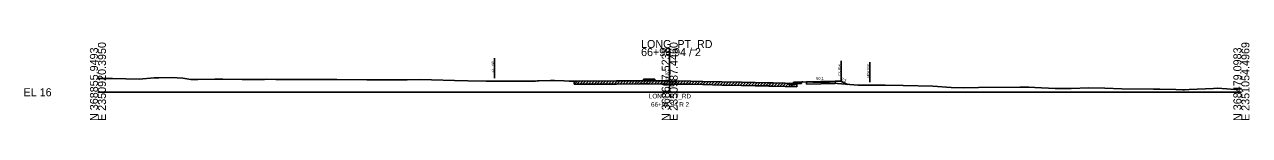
# Model space of a CAD drawing. Extents: x 974 to 2350744, y -10 to 368509.
# Drawn here: x 1974.3 to 2402.8, y 8990.3 to 9018.2 of the extents above; entities that cross this region are included whole.
import ezdxf

# ---------------------------------------------------------------- set-up
doc = ezdxf.new("R2010")
doc.units = 0
for name, color, linetype in [('RD_GPK_XS_Cell', 7, 'Continuous'), ('RD_PD_ConcMed', 7, 'Continuous'), ('RD_XS_CurbBase', 7, 'Continuous'), ('RD_XS_CurbFront', 7, 'Continuous'), ('RD_XS_CurbTop', 7, 'Continuous'), ('RD_XS_EarthShd', 7, 'Continuous'), ('RD_XS_ExGround', 7, 'Continuous'), ('RD_XS_ExPaveRet', 7, 'Continuous'), ('RD_XS_ExRW', 7, 'Continuous'), ('RD_XS_NewRW', 7, 'Continuous'), ('RD_XS_SW', 7, 'Continuous'), ('RD_XS_SWbase', 7, 'Continuous'), ('RD_XS_TieSlope', 7, 'Continuous'), ('RD_XS_TX_Elev_EX', 7, 'Continuous'), ('RD_XS_TX_Slope', 7, 'Continuous'), ('RD_XS_TX_Station', 7, 'Continuous'), ('RD_XS_TX_TOC', 7, 'Continuous')]:
    doc.layers.add(name, color=color, linetype=linetype)

msp = doc.modelspace()

# ---------------------------------------------------------------- linework, layer by layer
at = {"layer": 'RD_GPK_XS_Cell'}
for p, q in [((2200, 9000), (2200, 9015.4)), ((2000, 9000), (2200, 9000)), ((2200, 9000), (2400, 9000))]:
    msp.add_line(p, q, dxfattribs=at)
at = {"layer": 'RD_PD_ConcMed'}
for p, q in [((2190.85, 9004.54), (2194.85, 9004.53)), ((2190.85, 9004.04), (2190.85, 9004.54)), ((2194.85, 9004.03), (2194.85, 9004.53))]:
    msp.add_line(p, q, dxfattribs=at)
at = {"layer": 'RD_XS_CurbBase'}
for p, q in [((2243.86, 9003.55), (2243.86, 9002.55)), ((2243.28, 9002.55), (2241.86, 9002.63)), ((2243.86, 9002.55), (2243.28, 9002.55))]:
    msp.add_line(p, q, dxfattribs=at)
at = {"layer": 'RD_XS_CurbFront'}
msp.add_line((2241.86, 9002.63), (2241.86, 9003.13), dxfattribs=at)
at = {"layer": 'RD_XS_CurbTop'}
for p, q in [((2243.28, 9003.05), (2243.36, 9003.55)), ((2243.36, 9003.55), (2243.86, 9003.55)), ((2241.86, 9003.15), (2241.86, 9003.13)), ((2241.86, 9003.13), (2243.28, 9003.05))]:
    msp.add_line(p, q, dxfattribs=at)
at = {"layer": 'RD_XS_EarthShd'}
for p, q in [((2243.86, 9003.55), (2247.86, 9003.68)), ((2257.86, 9003.88), (2259.86, 9003.92))]:
    msp.add_line(p, q, dxfattribs=at)
at = {"layer": 'RD_XS_ExGround'}
msp.add_lwpolyline([(2000, 9004.77), (2001.58, 9004.78), (2002.13, 9004.82), (2005.1, 9004.74), (2014.42, 9004.54), (2019.72, 9005.02), (2021.34, 9005.07), (2025.69, 9005.13), (2029.73, 9004.87), (2032.47, 9004.49), (2034.89, 9004.49), (2040.9, 9004.59), (2043.67, 9004.51), (2050.45, 9004.5), (2058.27, 9004.5), (2058.83, 9004.51), (2062.24, 9004.42), (2072.9, 9004.46), (2075.41, 9004.44), (2083.59, 9004.41), (2094.01, 9004.34), (2095.98, 9004.34), (2101.29, 9004.33), (2102.51, 9004.32), (2108.18, 9004.33), (2112.95, 9004.42), (2116.65, 9004.34), (2124.73, 9004.14), (2129.38, 9003.97), (2135.77, 9003.84), (2145.53, 9003.92), (2153.11, 9003.92), (2153.72, 9003.93), (2154.24, 9003.94), (2158.37, 9004.06), (2159.66, 9004.13), (2163.07, 9003.97), (2164.8, 9003.9), (2166.03, 9003.92), (2167.71, 9003.92), (2181.41, 9004), (2189.43, 9004.03), (2192.6, 9004.04), (2197.3, 9003.99), (2200, 9003.97), (2207.35, 9003.91), (2211.61, 9003.81), (2218.3, 9003.65), (2225.15, 9003.51), (2229.91, 9003.4), (2234.46, 9003.33), (2234.8, 9003.32), (2236.23, 9003.29), (2244.59, 9003.09), (2245.14, 9003.09), (2246.08, 9003.08), (2246.18, 9003.58), (2246.58, 9003.58), (2250.11, 9003.56), (2251.3, 9003.54), (2253.12, 9003.47), (2261.55, 9002.77), (2265.98, 9002.53), (2272.59, 9002.5), (2275.39, 9002.5), (2281.71, 9002.33), (2292.03, 9002.07), (2298.44, 9001.69), (2302.88, 9001.58), (2308.04, 9001.7), (2322.46, 9001.73), (2324.97, 9001.77), (2325.69, 9001.74), (2327.69, 9001.65), (2334.86, 9001.34), (2340.49, 9001.27), (2346.64, 9001.56), (2352.22, 9001.44), (2358.21, 9001.23), (2369.23, 9001.13), (2371.46, 9001.14), (2377.12, 9000.94), (2379.57, 9000.9), (2380.12, 9000.88), (2381.76, 9001), (2390.21, 9001.34), (2391.52, 9001.48), (2394.92, 9001.16), (2397.59, 9000.99), (2400, 9001.16)], dxfattribs=at)
at = {"layer": 'RD_XS_ExPaveRet'}
for p, q in [((2166.56, 9002.78), (2167.71, 9003.92)), ((2166.56, 9002.78), (2166.56, 9003.92)), ((2167.56, 9002.78), (2168.71, 9003.93)), ((2168.56, 9002.78), (2169.71, 9003.93)), ((2169.56, 9002.79), (2170.71, 9003.94)), ((2170.56, 9002.79), (2171.71, 9003.94)), ((2171.56, 9002.8), (2172.71, 9003.95)), ((2172.56, 9002.8), (2173.71, 9003.95)), ((2173.56, 9002.81), (2174.71, 9003.96)), ((2174.56, 9002.81), (2175.71, 9003.96)), ((2175.56, 9002.82), (2176.71, 9003.97)), ((2176.56, 9002.83), (2177.71, 9003.97)), ((2177.56, 9002.83), (2178.71, 9003.98)), ((2178.56, 9002.84), (2179.71, 9003.99)), ((2179.56, 9002.84), (2180.71, 9003.99)), ((2180.56, 9002.85), (2181.71, 9004)), ((2181.56, 9002.85), (2182.71, 9004)), ((2182.56, 9002.86), (2183.71, 9004.01)), ((2183.56, 9002.86), (2184.71, 9004.01)), ((2184.56, 9002.87), (2185.71, 9004.02)), ((2185.56, 9002.87), (2186.71, 9004.02)), ((2186.56, 9002.88), (2187.71, 9004.03)), ((2187.56, 9002.88), (2188.71, 9004.03)), ((2188.56, 9002.89), (2189.71, 9004.03)), ((2189.56, 9002.89), (2190.71, 9004.04)), ((2190.56, 9002.89), (2191.71, 9004.04)), ((2191.56, 9002.89), (2192.71, 9004.04)), ((2192.56, 9002.89), (2193.7, 9004.03)), ((2193.56, 9002.89), (2194.7, 9004.02)), ((2194.56, 9002.88), (2195.7, 9004.01)), ((2195.56, 9002.87), (2196.7, 9004)), ((2196.56, 9002.86), (2197.7, 9003.99)), ((2197.56, 9002.85), (2198.7, 9003.98)), ((2198.56, 9002.84), (2199.7, 9003.98)), ((2199.56, 9002.83), (2200.7, 9003.97)), ((2200.56, 9002.83), (2201.7, 9003.96)), ((2201.56, 9002.82), (2202.7, 9003.95)), ((2202.56, 9002.81), (2203.7, 9003.94)), ((2203.56, 9002.8), (2204.7, 9003.93)), ((2204.56, 9002.79), (2205.7, 9003.93)), ((2205.56, 9002.78), (2206.7, 9003.92)), ((2206.56, 9002.78), (2207.69, 9003.9)), ((2207.56, 9002.76), (2208.68, 9003.88)), ((2208.56, 9002.74), (2209.68, 9003.86)), ((2209.56, 9002.72), (2210.68, 9003.83)), ((2210.56, 9002.69), (2211.68, 9003.81)), ((2211.56, 9002.67), (2212.68, 9003.78)), ((2212.56, 9002.64), (2213.68, 9003.76)), ((2213.56, 9002.62), (2214.68, 9003.74)), ((2214.56, 9002.6), (2215.68, 9003.71)), ((2215.56, 9002.57), (2216.68, 9003.69)), ((2216.56, 9002.55), (2217.68, 9003.66)), ((2217.56, 9002.52), (2218.68, 9003.64)), ((2218.56, 9002.5), (2219.68, 9003.62)), ((2219.56, 9002.48), (2220.68, 9003.6)), ((2220.56, 9002.46), (2221.68, 9003.58)), ((2221.56, 9002.44), (2222.68, 9003.56)), ((2222.56, 9002.42), (2223.68, 9003.54)), ((2223.56, 9002.4), (2224.68, 9003.52)), ((2224.56, 9002.38), (2225.68, 9003.5)), ((2225.56, 9002.36), (2226.68, 9003.48)), ((2166.56, 9002.78), (2167.71, 9002.78)), ((2167.71, 9002.78), (2181.41, 9002.85)), ((2181.41, 9002.85), (2189.43, 9002.89)), ((2189.43, 9002.89), (2192.6, 9002.89)), ((2192.6, 9002.89), (2197.3, 9002.85)), ((2197.3, 9002.85), (2200, 9002.83)), ((2200, 9002.83), (2207.35, 9002.77)), ((2207.35, 9002.77), (2211.61, 9002.67)), ((2211.61, 9002.67), (2218.3, 9002.51)), ((2218.3, 9002.51), (2225.15, 9002.37)), ((2225.15, 9002.37), (2229.91, 9002.26)), ((2226.56, 9002.34), (2227.68, 9003.45)), ((2227.56, 9002.31), (2228.68, 9003.43)), ((2228.56, 9002.29), (2229.68, 9003.41)), ((2229.56, 9002.27), (2230.69, 9003.39)), ((2229.91, 9002.26), (2234.46, 9002.19)), ((2230.56, 9002.25), (2231.69, 9003.38)), ((2231.56, 9002.23), (2232.69, 9003.36)), ((2232.56, 9002.22), (2233.69, 9003.34)), ((2233.56, 9002.2), (2234.69, 9003.33)), ((2234.46, 9002.19), (2234.8, 9002.18)), ((2234.56, 9002.19), (2235.68, 9003.3)), ((2234.8, 9002.18), (2236.23, 9002.15)), ((2235.56, 9002.16), (2236.68, 9003.28)), ((2236.23, 9002.15), (2244.48, 9001.95)), ((2236.56, 9002.14), (2237.68, 9003.26)), ((2237.56, 9002.12), (2238.68, 9003.23)), ((2238.56, 9002.09), (2239.68, 9003.21)), ((2239.56, 9002.07), (2240.68, 9003.18)), ((2240.56, 9002.04), (2241.68, 9003.16)), ((2241.56, 9002.02), (2242.68, 9003.14)), ((2242.56, 9002), (2243.68, 9003.11)), ((2244.48, 9003.09), (2244.48, 9001.95))]:
    msp.add_line(p, q, dxfattribs=at)
at = {"layer": 'RD_XS_ExRW'}
for p, q in [((2138.68, 9004.86), (2138.68, 9011.86)), ((2260, 9003.9), (2260, 9010.9))]:
    msp.add_line(p, q, dxfattribs=at)
at = {"layer": 'RD_XS_NewRW'}
msp.add_line((2270, 9003.51), (2270, 9010.51), dxfattribs=at)
at = {"layer": 'RD_XS_SW'}
msp.add_line((2247.86, 9003.68), (2257.86, 9003.88), dxfattribs=at)
at = {"layer": 'RD_XS_SWbase'}
for p, q in [((2247.86, 9003.68), (2247.86, 9002.85)), ((2257.86, 9003.05), (2257.86, 9003.88)), ((2247.86, 9002.85), (2257.86, 9003.05))]:
    msp.add_line(p, q, dxfattribs=at)
at = {"layer": 'RD_XS_TieSlope'}
msp.add_line((2259.86, 9003.92), (2262.24, 9002.73), dxfattribs=at)

# ---------------------------------------------------------------- texts
at = {"layer": 'RD_GPK_XS_Cell'}
for s, p in [('E 2350920.3950', (2002.8, 8990)), ('E 2350987.4460', (2202.8, 8990)), ('E 2351054.4969', (2402.8, 8990)), ('N 368855.9493', (2000, 8990)), ('N 368667.5238', (2200, 8990)), ('N 368479.0983', (2400, 8990))]:
    msp.add_text(s, height=2.8, rotation=90, dxfattribs=at).set_placement(p)
for s, p in [('LONG_PT_RD', (2190, 9015.4)), ('66+96.94 / 2', (2190, 9012.6)), ('EL 16', (1974, 8998.6))]:
    msp.add_text(s, height=2.8, dxfattribs=at).set_placement(p)
at = {"layer": 'RD_XS_ExRW'}
for p in [(2138.43, 9006.82), (2259.75, 9005.85)]:
    msp.add_text('EX. R/W ', height=0.75, rotation=90, dxfattribs=at).set_placement(p)
at = {"layer": 'RD_XS_NewRW'}
msp.add_text('NEW R/W ', height=0.75, rotation=90, dxfattribs=at).set_placement((2269.75, 9005.1))
at = {"layer": 'RD_XS_TX_Elev_EX'}
msp.add_text('19.97', height=1, rotation=90, dxfattribs=at).set_placement((2199.51, 9003.97))
at = {"layer": 'RD_XS_TX_Slope'}
for s, rotation, p in [('50:1', 1.1458, (2251.24, 9004.28)), ('2:1', 333.4349, (2259.87, 9004.3))]:
    msp.add_text(s, height=1, rotation=rotation, dxfattribs=at).set_placement(p)
at = {"layer": 'RD_XS_TX_Station'}
for s, p in [('LONG_PT_RD', (2192.72, 8997.87)), ('66+96.94 R 2', (2193.48, 8994.97))]:
    msp.add_text(s, height=1.6, dxfattribs=at).set_placement(p)
at = {"layer": 'RD_XS_TX_TOC'}
msp.add_text('SWR', height=0.05, dxfattribs=at).set_placement((2247.71, 9003.63))

doc.saveas('drawing.dxf')
